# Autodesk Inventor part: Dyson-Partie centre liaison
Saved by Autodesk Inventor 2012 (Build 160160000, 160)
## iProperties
Created: 2012-11
Part Number: Dyson-Partie centre liaison
Material: Default
Document SubType Name: Modeling
Designer: Administrateur
Density: 1 g/cm^3
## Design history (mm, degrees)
node "Dyson-Partie centre liaison1"
node "Dyson-Partie centre liaison"
node "Base1"
